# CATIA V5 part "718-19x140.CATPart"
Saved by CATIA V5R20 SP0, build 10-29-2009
Part number: 718-19x140
Definition: NONE
Nomenclature: 718-19x140
Source: Unknown
Description: 718-19x140
Bounding box of the stored display mesh (mm): x 0 to 163, y -12.5 to 12.5, z -12.5 to 12.5
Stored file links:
  C:\Users\Utente\Desktop\IO LAVORO\3D X SITO CF\X SITO\718\718-19x140.CATPart

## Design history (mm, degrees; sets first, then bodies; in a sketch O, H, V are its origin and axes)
Body1 "718-19x140" (main body)
  Solid1: solid without history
